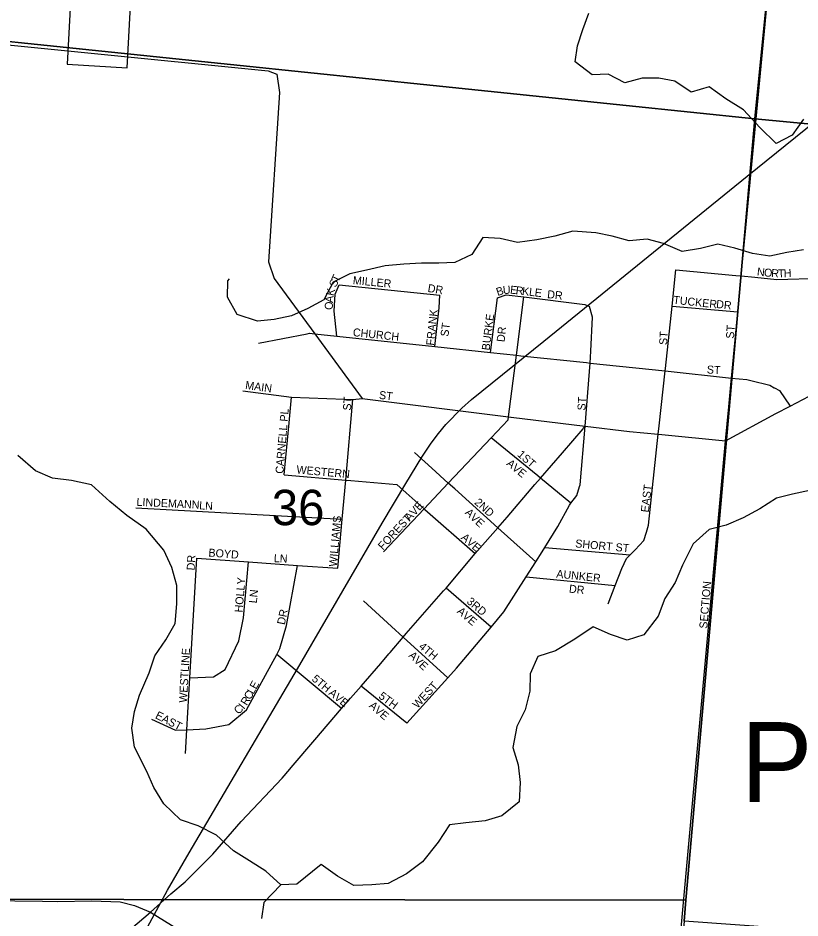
# Model space of a CAD drawing. Extents: x 1310247 to 1664935, y 284496 to 704931.
# Drawn here: x 1452617 to 1457504, y 497520 to 503144 of the extents above; entities that cross this region are included whole.
import ezdxf

# ---------------------------------------------------------------- set-up
doc = ezdxf.new("R2010")
doc.units = 0
for name, color, linetype in [('GM_P_State_Shield', 7, 'Continuous'), ('GM_X_Corporation_Text', 7, 'Continuous'), ('GM_X_County', 7, 'Continuous'), ('GM_X_County_Road', 7, 'Continuous'), ('GM_X_Major_Lake_Text', 7, 'Continuous'), ('GM_X_Minor_River_Text', 7, 'Continuous'), ('GM_X_Rail_Line', 7, 'Continuous'), ('GM_X_State_Route', 7, 'Continuous'), ('GM_X_US_Location', 7, 'Continuous')]:
    doc.layers.add(name, color=color, linetype=linetype)

msp = doc.modelspace()

# ---------------------------------------------------------------- linework, layer by layer
at = {"layer": 'GM_P_State_Shield'}
for points in [[(1457039, 500502.2), (1457039, 500502.2), (1457353.3, 500672.2), (1457442.3, 500718.7), (1457641.1, 500822.7), (1457788.4, 500906.3), (1457870.7, 500953), (1457886.6, 500962), (1458088.9, 501069.9), (1458140, 501097.2), (1458367.1, 501218.8), (1458397.2, 501236.2)], [(1454935.2, 499170.1), (1454943.4, 499179.8), (1455024.3, 499275.5), (1455043.2, 499297.9), (1455277.2, 499563.9), (1455292.6, 499582), (1455474.8, 499797.7), (1455488.9, 499814.3), (1455615.6, 499958.9), (1455673.7, 500025.1), (1455846.2, 500228.2), (1455882, 500268.9), (1456020.8, 500427.2), (1456148.7, 500576.7)], [(1456148.7, 500576.7), (1456152.1, 500580.7), (1456162.5, 500592.8), (1456438.6, 500560.9), (1456618.8, 500542.8), (1456640.7, 500540.6), (1457039, 500502.2)], [(1454315.9, 498450.4), (1454323.8, 498459.7), (1454472.1, 498633.5), (1454639.7, 498828.4), (1454696, 498893.8), (1454761.7, 498969.2), (1454884.9, 499110.6), (1454935.2, 499170.1)], [(1453820.6, 497905.3), (1453835.2, 497919.9), (1454011.2, 498124.2), (1454268.7, 498395), (1454315.9, 498450.4)], [(1453154.5, 497308.9), (1453279.1, 497415.9), (1453444.5, 497556.5), (1453571.3, 497670.9), (1453660.8, 497747), (1453735.3, 497820), (1453820.6, 497905.3)]]:
    msp.add_lwpolyline(points, dxfattribs=at)
at = {"layer": 'GM_X_Corporation_Text'}
for points in [[(1457226.1, 502470.7), (1457392.9, 504225.9), (1457408.1, 504386.1)], [(1449170, 503026.9), (1449179.3, 503027.1), (1449386.5, 503032.4), (1450225.2, 503023.7), (1450634.3, 503014.7), (1451114.6, 503041.8), (1451674.6, 503044.8), (1451883.3, 503043.2), (1454180.8, 502814.4), (1454234.4, 502792.8), (1454251.4, 502677.9), (1454182.9, 501621.2), (1454218.2, 501515.9), (1454471.2, 501170.6), (1454767.9, 500765.9)], [(1457165.4, 501832.3), (1457226.1, 502470.7)], [(1457074.4, 500874.6), (1457076.3, 500894.5), (1457115.5, 501307.2), (1457136.9, 501532.8), (1457165.4, 501832.3)], [(1456662.9, 500954.9), (1456704.6, 501344.1), (1456728.8, 501570.3)], [(1456728.8, 501570.3), (1457103, 501536.2), (1457136.9, 501532.8), (1457221.2, 501524.4), (1457221.6, 501524.3)], [(1457221.6, 501524.3), (1457359.1, 501510.6), (1457635.9, 501518.7), (1457737.2, 501518.1), (1458012.8, 501516.6)], [(1454608.7, 501156.1), (1454592, 501311.3), (1454598.4, 501419.5), (1454623.7, 501477.1)], [(1454623.7, 501477.1), (1455253.8, 501411.4)], [(1455223, 501091), (1455250.1, 501333.2), (1455253.8, 501411.4)], [(1455570.6, 501054.1), (1455614.3, 501395.6)], [(1455614.3, 501395.6), (1455668.9, 501414.5), (1455778.6, 501400.9), (1456158.8, 501353.8), (1456188.6, 501341.1)], [(1455679.7, 500633.2), (1455680.1, 500633.6), (1455682.4, 500651.5), (1455731.9, 501037), (1455778.6, 501400.9)], [(1456196.3, 501061.8), (1456196.3, 501062.8), (1456207.2, 501274.5), (1456188.6, 501341.1)], [(1456704.6, 501344.1), (1457115.5, 501307.2)], [(1454120.6, 501112.7), (1454423.6, 501171.1), (1454424.7, 501171.4)], [(1454424.7, 501171.4), (1454438.7, 501174.1), (1454471.2, 501170.6), (1454608.7, 501156.1), (1455223, 501091), (1455570.6, 501054.1), (1455731.9, 501037), (1455758.7, 501034.2), (1455759.3, 501034.1)], [(1456162.5, 500592.8), (1456162.5, 500592.8), (1456189.8, 500935.7), (1456192.5, 500988.2), (1456196.3, 501061.8)], [(1455759.3, 501034.1), (1456169.6, 500990.6), (1456170, 500990.6)], [(1456170, 500990.6), (1456192.5, 500988.2), (1456661.2, 500938.5), (1457076.3, 500894.5), (1457171.1, 500884.5), (1457196.2, 500878.4)], [(1456624.5, 500596), (1456661.2, 500938.5), (1456662.9, 500954.6), (1456662.9, 500954.9)], [(1457059.2, 500715), (1457074.4, 500874.6)], [(1457196.2, 500878.4), (1457196.2, 500878.4), (1457316.7, 500849.3), (1457343.6, 500834.2)], [(1457343.6, 500834.2), (1457344.1, 500833.9), (1457376.2, 500815.9), (1457442.3, 500718.7)], [(1454021.9, 500813.8), (1454325.8, 500775.1), (1454658, 500762.8), (1454659.7, 500762.7)], [(1454311, 500613.6), (1454325.8, 500775.1)], [(1454615.5, 499705.3), (1454643.1, 500012.3), (1454665.1, 500257), (1454710.5, 500760.8)], [(1454659.7, 500762.7), (1454710.5, 500760.8), (1454767.9, 500765.9), (1455682.4, 500651.5), (1455697.9, 500649.6), (1455700.2, 500649.3)], [(1457039, 500502.2), (1457059.2, 500715)], [(1454281.3, 500290.4), (1454311, 500613.6), (1454311, 500613.6)], [(1455183.8, 500107.8), (1455183.9, 500107.9), (1455306.5, 500237.9), (1455573.9, 500521.1), (1455679.7, 500633.2)], [(1455700.2, 500649.3), (1456162.5, 500592.8)], [(1456126.9, 500215.9), (1456127.1, 500216.5), (1456130.4, 500226.6), (1456162.5, 500592.8)], [(1456544.3, 499931.2), (1456544.5, 499931.5), (1456558, 499974.6), (1456618.8, 500542.8), (1456624.5, 500595.4), (1456624.5, 500596)], [(1455865.1, 500282.8), (1455573.9, 500521.1)], [(1456930.8, 499312.8), (1457039, 500502.2)], [(1455202.6, 500331.7), (1455094.3, 500429.5)], [(1455347, 500201.3), (1455306.5, 500237.9), (1455202.6, 500331.7), (1455202.6, 500331.7)], [(1454281.3, 500290.4), (1454665.1, 500257), (1454697.5, 500254.2), (1454697.8, 500254.1)], [(1456073.1, 500112.5), (1455882, 500268.9), (1455865.1, 500282.8), (1455865.1, 500282.8)], [(1454697.8, 500254.1), (1454983.7, 500229.2), (1455042.6, 500177.4), (1455042.9, 500177.1)], [(1455047.7, 498736.7), (1455304.1, 499021.6), (1455357.9, 499081.3), (1455573.4, 499337.9), (1455654.2, 499434.1), (1455792.9, 499651.6), (1455852.5, 499745), (1455892.8, 499808.3), (1455909.2, 499834.8), (1455990.5, 499966.7), (1456063.5, 500099.6), (1456073.1, 500112.5), (1456109, 500160.8), (1456126.9, 500215.9)], [(1455042.9, 500177.1), (1455155.7, 500078.1), (1455160.5, 500073.9), (1455160.7, 500073.6)], [(1455635.8, 499940.6), (1455635.8, 499940.6), (1455615.6, 499958.9), (1455347, 500201.3), (1455347, 500201.3)], [(1454900.4, 499807.5), (1455155.7, 500078.1), (1455183.8, 500107.8)], [(1453352.5, 500083.7), (1454643.1, 500012.3)], [(1455160.7, 500073.6), (1455474.8, 499797.7)], [(1455852.5, 499745), (1455635.8, 499940.6)], [(1456459.1, 499806.5), (1456459.8, 499807.2), (1456474.5, 499821.8), (1456527.9, 499878.9), (1456544.3, 499931.2)], [(1455909.2, 499834.8), (1456442.4, 499789.9)], [(1453664.2, 498547.8), (1453672.8, 498696.6), (1453691.5, 499020.8), (1453734.7, 499768.4)], [(1453734.7, 499768.4), (1454057.8, 499745.3), (1454364, 499723.3), (1454615.5, 499705.3)], [(1456304.9, 499484.3), (1456349.4, 499597.5), (1456391.8, 499705.2), (1456419.2, 499766.8), (1456442.4, 499789.9), (1456459.1, 499806.5)], [(1453452.3, 498763), (1453601.2, 498693.6), (1453672.8, 498696.6), (1453791.8, 498701.6), (1453934.8, 498728.6), (1454045, 498820.5), (1454233.7, 499166.6), (1454253.8, 499203.4), (1454295, 499349), (1454364, 499723.3)], [(1453691.5, 499020.8), (1453839, 499027.6), (1453912.1, 499072.2), (1453996.2, 499253), (1454025.4, 499396.9), (1454057.8, 499745.3)], [(1455792.9, 499651.6), (1456349.4, 499597.5)], [(1455573.4, 499337.9), (1455292.6, 499582)], [(1454951.7, 499341.3), (1454951.7, 499341.3), (1454775.5, 499501.2)], [(1455304.1, 499021.6), (1455024.3, 499275.5), (1454951.7, 499341.3)], [(1455748.4, 486822.8), (1455748.4, 486822.8), (1455848.8, 487858.1), (1455854.9, 487922.2), (1456028.6, 489717.3), (1456273.6, 492189.5), (1456526.3, 494865.6), (1456930.8, 499312.8)], [(1454639.7, 498828.4), (1454233.7, 499166.6)], [(1455047.7, 498736.7), (1454761.7, 498969.2)], [(1450821.2, 497647.8), (1450897.9, 497648.5), (1451559.9, 497639.6), (1452770.9, 497625.1)], [(1452770.9, 497625.1), (1452862.9, 497624), (1453078.8, 497628.4), (1453254.7, 497621.2), (1453344.4, 497598), (1453444.5, 497556.5)], [(1453444.5, 497556.5), (1453576.6, 497476.3), (1453711.6, 497389.5), (1453791.5, 497320.9)]]:
    msp.add_lwpolyline(points, dxfattribs=at)
at = {"layer": 'GM_X_County'}
for points in [[(1452467.3, 508458.4), (1457766.6, 507956.1), (1457222.9, 502513.6), (1451992.5, 503054.9), (1451866.7, 503067.5)], [(1457766.6, 507956.1), (1463120.7, 507398.7), (1462858.9, 505825.7), (1462644, 502004.5), (1462624, 502004.9), (1457222.9, 502513.6)], [(1451992.5, 503054.9), (1457222.9, 502513.6), (1456790.6, 497630.8), (1451519.4, 497637), (1451497.4, 497635.4)], [(1457222.9, 502513.6), (1462624, 502004.9), (1462164.5, 497362.7), (1462139.6, 497115.2), (1456780, 497501.1), (1456790.6, 497630.8)], [(1456790.6, 497630.8), (1456780, 497501.1), (1456291.7, 492217.5), (1451025.9, 492295.4), (1451519.4, 497637)]]:
    msp.add_lwpolyline(points, close=True, dxfattribs=at)
at = {"layer": 'GM_X_Major_Lake_Text'}
msp.add_lwpolyline([(1452924.3, 502856.1), (1453299.8, 502832.6), (1453358.9, 503958.6), (1452983.9, 503984.8)], close=True, dxfattribs=at)
at = {"layer": 'GM_X_Minor_River_Text'}
for points in [[(1457525.5, 502512.8), (1457455.3, 502412.6), (1457355, 502360.5), (1457252.7, 502460.7), (1457150.4, 502570.9), (1457040, 502639.1), (1456937.7, 502715.2), (1456823.4, 502681.2), (1456723.1, 502749.3), (1456622.7, 502767.4), (1456518.4, 502767.4), (1456410.1, 502739.3), (1456305.8, 502793.4), (1456205.4, 502789.4), (1456099.1, 502869.6), (1456113.2, 502969.8), (1456147.3, 503072), (1456185.4, 503174.3)], [(1457525.5, 501695), (1457421.1, 501679), (1457316.8, 501656.9), (1457208.5, 501673), (1457098.1, 501705), (1456991.8, 501731.1), (1456881.5, 501703), (1456767.1, 501685), (1456650.8, 501735.1), (1456548.4, 501763.1), (1456436.1, 501751.1), (1456329.8, 501781.2), (1456227.4, 501801.2), (1456085, 501813.2), (1455972.7, 501781.2), (1455860.3, 501757.1), (1455737.9, 501741.1), (1455629.6, 501767.1), (1455521.2, 501773.1), (1455453, 501666.9), (1455346.7, 501616.8), (1455246.4, 501612.8), (1455138, 501612.8), (1455027.7, 501606.7), (1454911.3, 501594.7), (1454795, 501568.6), (1454690.7, 501546.6), (1454586.3, 501494.5), (1454528.1, 501382.2), (1454427.8, 501328.1), (1454325.5, 501284), (1454217.1, 501260), (1454114.8, 501249.9), (1453986.4, 501292), (1453926.2, 501400.2), (1453928.3, 501502.5), (1453938.3, 501514.5)], [(1454259, 497728.1), (1454166.8, 497812.3), (1454064.4, 497876.4), (1453964.1, 497940.6), (1453857.8, 498038.8), (1453743.4, 498096.9), (1453633.1, 498133), (1453528.8, 498233.2), (1453466.6, 498335.4), (1453422.5, 498435.7), (1453346.2, 498588), (1453328.2, 498706.3), (1453344.2, 498810.5), (1453376.3, 498912.7), (1453436.5, 499053), (1453472.7, 499159.3), (1453540.9, 499259.5), (1453599.1, 499359.7), (1453609.1, 499484), (1453609.1, 499598.2), (1453579, 499710.5), (1453528.9, 499818.7), (1453418.5, 499951), (1453298.2, 500035.2), (1453191.8, 500123.4), (1453075.5, 500227.6), (1452951.1, 500253.7), (1452832.7, 500269.7), (1452726.4, 500313.8), (1452616, 500410)], [(1457563.5, 500191.7), (1457457.2, 500169.6), (1457356.8, 500143.5), (1457252.5, 500077.4), (1457148.2, 500021.3), (1457043.9, 499975.2), (1456937.5, 499947.1), (1456837.2, 499858.9), (1456769, 499724.6), (1456724.8, 499616.4), (1456658.6, 499516.1), (1456618.5, 499405.9), (1456528.2, 499289.6), (1456423.9, 499255.6), (1456319.6, 499291.6), (1456211.2, 499339.8), (1456096.9, 499261.6), (1455976.5, 499189.4), (1455866.2, 499155.3), (1455818, 499045.1), (1455816, 498936.8), (1455785.9, 498820.6), (1455733.7, 498716.3), (1455709.6, 498586.1), (1455743.7, 498477.8), (1455755.8, 498367.6), (1455749.7, 498245.3), (1455641.4, 498159.1), (1455537.1, 498127), (1455416.7, 498115), (1455314.4, 498103), (1455242.1, 497994.7), (1455145.8, 497870.5), (1455045.5, 497796.3), (1454931.1, 497736.1), (1454828.8, 497728.1), (1454716.5, 497724.1), (1454614.2, 497782.2), (1454511.8, 497854.4), (1454359.3, 497732.1), (1454259, 497728.1), (1454152.7, 497617.9), (1454138.6, 497517.6)]]:
    msp.add_lwpolyline(points, dxfattribs=at)
at = {"layer": 'GM_X_State_Route'}
for points in [[(1453686.7, 497928.1), (1454364, 499077.6), (1454893.7, 499987.5), (1455041.9, 500234.5), (1455140.7, 500399.8), (1455200, 500487.4), (1455244.1, 500547.3), (1455290.9, 500603.3), (1455390.4, 500705.4), (1455450.3, 500760.1), (1455903.5, 501125), (1457174.2, 502155.1), (1460745.5, 505039.7), (1463650.1, 507391.2), (1464411.8, 508005.7), (1466383.2, 509596.7), (1466689.7, 509844.2), (1466931.9, 510028.4), (1467213.6, 510216.7), (1467574.2, 510422.8), (1468046.5, 510646.4), (1468144.5, 510687.7)], [(1449216.5, 489604.8), (1449465.1, 490068.7), (1449751.6, 490607.4), (1451083.6, 493089), (1451204.2, 493315.9), (1452392.4, 495533.5), (1453153.5, 496958.6), (1453551.5, 497694.7), (1453686.7, 497928.1)]]:
    msp.add_lwpolyline(points, dxfattribs=at)

# ---------------------------------------------------------------- texts
at = {"layer": 'GM_X_County_Road'}
msp.add_text('Pine', height=499.95, rotation=0.0002, dxfattribs=at).set_placement((1457135.7, 498244.1))
at = {"layer": 'GM_X_Rail_Line'}
for s, rotation, p in [('N', 354.1763, (1457233.6, 501535.1)), ('O', 354.1909, (1457277.4, 501530.7)), ('R', 355.7712, (1457322.7, 501526.1)), ('T', 1.5009, (1457367.7, 501523)), ('H', 2.5859, (1457403.9, 501524)), ('S', 65.3752, (1454603.7, 501457.3)), ('T', 65.3752, (1454618.4, 501489.3)), ('MILLER', 354.5063, (1454707.9, 501481.7)), ('K', 76.5428, (1454589.6, 501404.6)), ('DR', 350.5436, (1455174.9, 501433.2)), ('B', 17.7206, (1455614.7, 501407)), ('U', 5.2083, (1455649.6, 501418.5)), ('E', 354.0611, (1455690.9, 501422.5)), ('R', 353.4051, (1455725.8, 501418.9)), ('K', 353.4064, (1455765.1, 501414.4)), ('L', 353.4003, (1455808.8, 501409.3)), ('E', 353.4097, (1455843.8, 501405.3)), ('A', 83.9879, (1454585.3, 501362.6)), ('DR', 353.9934, (1455922.5, 501394.3)), ('TUCKER', 353.8839, (1456710.1, 501359.1)), ('O', 87.7104, (1454583.6, 501319.5)), ('DR', 353.9946, (1456978.4, 501332.7)), ('FRANK', 83.9259, (1455216.9, 501095.6)), ('BURKE', 82.7239, (1455564.5, 501065)), ('ST', 82.8783, (1455306.7, 501151.1)), ('CHURCH', 353.9942, (1454708.1, 501156.7)), ('DR', 83.982, (1455657.9, 501117.4)), ('ST', 86.4118, (1456673.3, 501099.6)), ('ST', 86.4254, (1457091.3, 501139.1)), ('ST', 356.4262, (1456920.8, 500923.6)), ('MAIN', 352.3021, (1454035.1, 500826.7)), ('ST', 86.4262, (1454697.7, 500690.3)), ('ST', 352.8649, (1454871, 500765.1)), ('ST', 86.4262, (1456162.9, 500690.3)), ('CARNELL PL', 85.2366, (1454275.3, 500294.5)), ('1ST', 318.581, (1455734.1, 500410.8)), ('WESTERN', 354.8053, (1454355.9, 500298.7)), ('AVE', 320.443, (1455665.9, 500353.5)), ('EAST', 83.4837, (1456558.9, 500052.8)), ('LINDEMANN', 357.2726, (1453356.7, 500096.2)), ('LN', 356.989, (1453748.3, 500074.2)), ('AVE', 47.7248, (1455065.3, 499996.5)), ('2ND', 318.017, (1455465.8, 500111.6)), ('FOREST', 47.3521, (1454898.1, 499816.1)), ('AVE', 316.3964, (1455406.6, 500049.1)), ('WILLIAMS', 85.0298, (1454609.7, 499713.8)), ('AVE', 319.1826, (1455382, 499891.7)), ('SHORT ST', 354.7258, (1456098.3, 499836.7)), ('BOYD', 355.6039, (1453805.8, 499779.5)), ('DR', 86.8215, (1453720.9, 499691.5)), ('LN', 356.9884, (1454214.8, 499744.3)), ('AUNKER', 354.0936, (1455979.6, 499647.5)), ('HOLLY', 85.1382, (1454020.1, 499427.8)), ('DR', 353.9832, (1456058.7, 499554.1)), ('SECTION', 85.1585, (1456924.1, 499326.6)), ('LN', 83.9946, (1454109.1, 499485.1)), ('3RD', 319.639, (1455417.2, 499491.3)), ('DR', 78.6838, (1454284.3, 499349.6)), ('AVE', 319.1826, (1455356.6, 499430.6)), ('WESTLINE', 86.6822, (1453672.5, 498864.3)), ('4TH', 319.8959, (1455117.9, 499209.8)), ('AVE', 316.3964, (1455054.6, 499155.9)), ('5TH', 319.9026, (1454449.1, 499007.4)), ('E', 61.2912, (1454105.4, 498945.8)), ('WEST', 47.1199, (1455113.8, 498826.2)), ('C', 61.2912, (1454069.5, 498880.3)), ('L', 61.2912, (1454088.5, 498915)), ('AVE', 320.7133, (1454554.6, 498919.4)), ('5TH', 323.1249, (1454866.7, 498897.7)), ('R', 57.5921, (1454046.5, 498843.8)), ('AVE', 319.1826, (1454806.6, 498841)), ('EAST', 332.7037, (1453470.6, 498770.9)), ('C', 42.796, (1453994.3, 498789.2)), ('I', 50.1941, (1454028.2, 498821.2))]:
    msp.add_text(s, height=50, rotation=rotation, dxfattribs=at).set_placement(p)
at = {"layer": 'GM_X_US_Location'}
msp.add_text('36', height=221, rotation=0, dxfattribs=at).set_placement((1454203.3, 499975.1))

doc.saveas('drawing.dxf')
